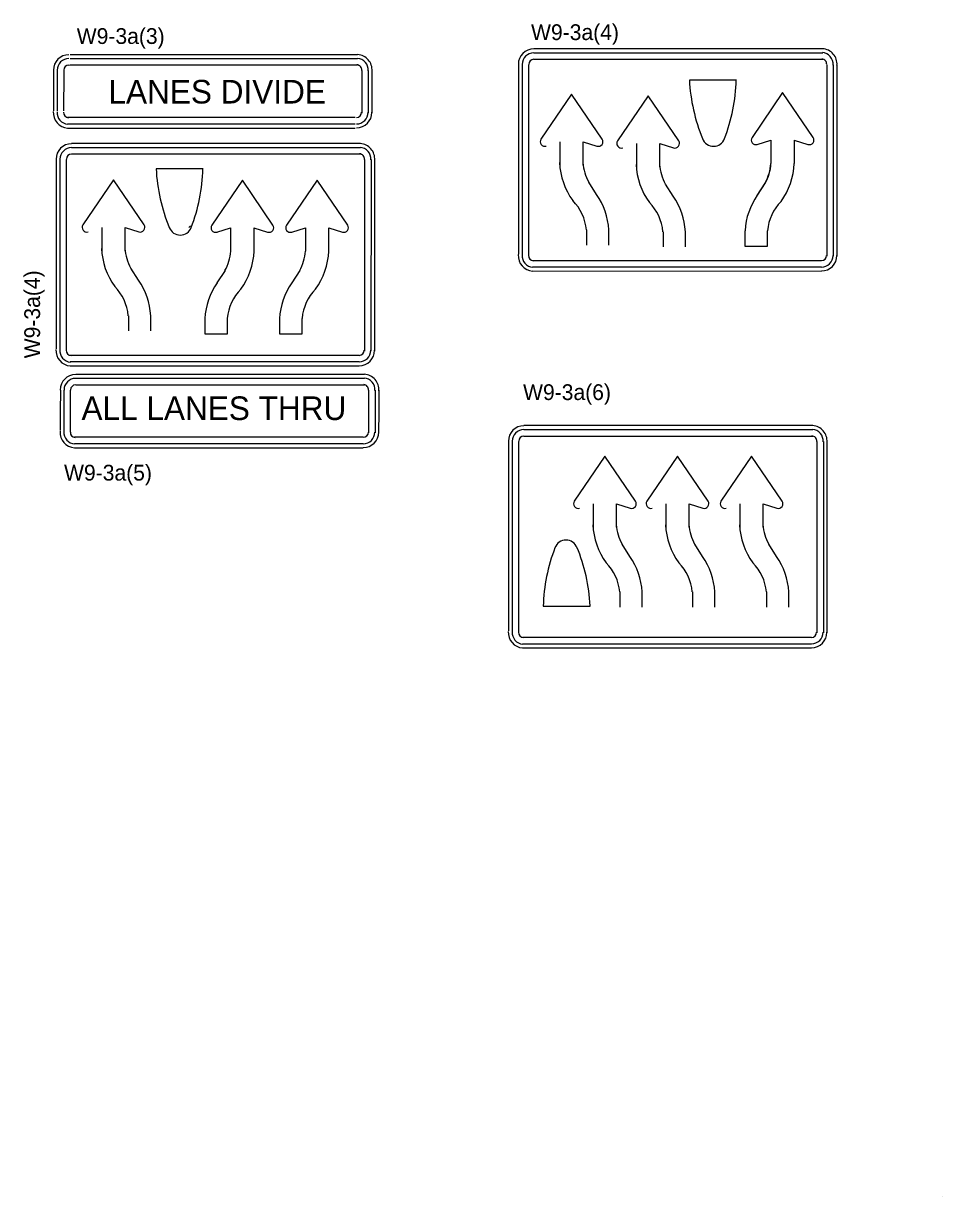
# Model space of a CAD drawing. Extents: x 1531.44 to 1538.58, y 1529.59 to 1539.3.
# Drawn here: x 1535.089 to 1538.584, y 1529.592 to 1534.054 of the extents above; entities that cross this region are included whole.
import ezdxf

# ---------------------------------------------------------------- set-up
doc = ezdxf.new("R2010")
doc.units = 0
for name, color, linetype in [('DETL-LINE', 7, 'Continuous'), ('DETL-NOTE', 7, 'Continuous'), ('TTLB-TEXT', 7, 'Continuous')]:
    doc.layers.add(name, color=color, linetype=linetype)

msp = doc.modelspace()

# ---------------------------------------------------------------- linework, layer by layer
at = {"layer": 'DETL-LINE'}
for p, q in [((1536.3596, 1533.9349), (1535.2666, 1533.9349)), ((1538.1285, 1533.9573), (1537.0299, 1533.9573)), ((1537.0299, 1533.9423), (1538.1285, 1533.9423)), ((1535.2613, 1533.8954), (1535.2658, 1533.8962)), ((1535.2658, 1533.8962), (1536.3596, 1533.8962)), ((1535.2666, 1533.9208), (1536.3596, 1533.92)), ((1536.9713, 1533.8966), (1536.9713, 1533.1767)), ((1536.9863, 1533.1736), (1536.9863, 1533.8966)), ((1537.0109, 1533.1719), (1537.0109, 1533.8966)), ((1537.0299, 1533.9177), (1538.1285, 1533.9177)), ((1537.0299, 1533.9174), (1537.0299, 1533.9177)), ((1538.1444, 1533.8966), (1538.1444, 1533.1688)), ((1538.169, 1533.8966), (1538.169, 1533.1688)), ((1538.1831, 1533.1688), (1538.1831, 1533.8966)), ((1535.2033, 1533.8751), (1535.2033, 1533.7932)), ((1535.2182, 1533.7932), (1535.2182, 1533.8751)), ((1535.242, 1533.8751), (1535.242, 1533.7932)), ((1536.3754, 1533.8751), (1536.3754, 1533.7932)), ((1536.4001, 1533.8751), (1536.4001, 1533.7932)), ((1536.415, 1533.7932), (1536.415, 1533.8751)), ((1537.8002, 1533.8381), (1537.6215, 1533.8381)), ((1535.2033, 1533.7924), (1535.2033, 1533.7211)), ((1535.2174, 1533.7211), (1535.2174, 1533.7924)), ((1535.242, 1533.7211), (1535.242, 1533.7924)), ((1536.3754, 1533.7924), (1536.3754, 1533.7123)), ((1536.4001, 1533.7924), (1536.4001, 1533.7123)), ((1536.415, 1533.7123), (1536.415, 1533.7924)), ((1537.1736, 1533.7853), (1537.0566, 1533.6137)), ((1537.2898, 1533.6137), (1537.1736, 1533.7853)), ((1537.4649, 1533.7783), (1537.3478, 1533.6067)), ((1537.581, 1533.6067), (1537.4649, 1533.7783)), ((1537.9762, 1533.7906), (1537.86, 1533.6199)), ((1538.0923, 1533.6199), (1537.9762, 1533.7906)), ((1536.3499, 1533.6956), (1535.2561, 1533.6956)), ((1536.3499, 1533.6709), (1535.2561, 1533.6709)), ((1535.2561, 1533.656), (1536.3499, 1533.656)), ((1536.3702, 1533.597), (1535.2715, 1533.597)), ((1535.2715, 1533.582), (1536.3702, 1533.582)), ((1537.1287, 1533.604), (1537.1287, 1533.5152)), ((1537.2176, 1533.5152), (1537.2176, 1533.604)), ((1537.2176, 1533.604), (1537.2695, 1533.5873)), ((1537.2695, 1533.5873), (1537.2698, 1533.5876)), ((1537.42, 1533.597), (1537.42, 1533.5081)), ((1537.5089, 1533.5081), (1537.5089, 1533.597)), ((1537.5089, 1533.597), (1537.5608, 1533.5803)), ((1537.5608, 1533.5803), (1537.5611, 1533.5805)), ((1537.8794, 1533.5935), (1537.9313, 1533.6102)), ((1537.9313, 1533.6102), (1537.9313, 1533.5213)), ((1537.9313, 1533.6093), (1537.9313, 1533.5204)), ((1538.0202, 1533.6102), (1538.0721, 1533.5935)), ((1538.021, 1533.5213), (1538.021, 1533.6102)), ((1535.213, 1533.5363), (1535.213, 1532.8164)), ((1535.2279, 1532.8131), (1535.2279, 1533.5363)), ((1535.2526, 1532.8114), (1535.2526, 1533.5363)), ((1535.2715, 1533.5574), (1536.3702, 1533.5574)), ((1535.2715, 1533.5569), (1535.2715, 1533.5574)), ((1536.386, 1533.5363), (1536.386, 1532.8076)), ((1536.4106, 1533.5363), (1536.4098, 1532.8076)), ((1536.4247, 1532.8076), (1536.4247, 1533.5363)), ((1535.5931, 1533.4993), (1535.594, 1533.5002)), ((1535.7718, 1533.5002), (1535.5931, 1533.5002)), ((1538.0206, 1533.5211), (1538.021, 1533.5213)), ((1535.4312, 1533.4588), (1535.3142, 1533.2872)), ((1535.5474, 1533.2872), (1535.4312, 1533.4588)), ((1535.9214, 1533.4571), (1535.8052, 1533.2864)), ((1536.0375, 1533.2864), (1535.9214, 1533.4571)), ((1536.2056, 1533.4571), (1536.0894, 1533.2864)), ((1536.3218, 1533.2864), (1536.2056, 1533.4571)), ((1537.2686, 1533.4034), (1537.2387, 1533.45)), ((1537.5599, 1533.3964), (1537.53, 1533.443)), ((1537.9102, 1533.4474), (1537.8794, 1533.4008)), ((1537.8794, 1533.3999), (1537.9102, 1533.4465)), ((1535.3863, 1533.2776), (1535.3863, 1533.1887)), ((1535.4752, 1533.1887), (1535.4752, 1533.2776)), ((1535.4752, 1533.2776), (1535.5271, 1533.2608)), ((1535.7172, 1533.2776), (1535.7242, 1533.2846)), ((1535.8246, 1533.26), (1535.8765, 1533.2767)), ((1535.8765, 1533.2767), (1535.8765, 1533.1878)), ((1535.9654, 1533.2767), (1536.0173, 1533.26)), ((1535.9662, 1533.1878), (1535.9662, 1533.2767)), ((1536.1088, 1533.26), (1536.1607, 1533.2767)), ((1536.1607, 1533.2767), (1536.1607, 1533.1878)), ((1536.2496, 1533.2767), (1536.3015, 1533.26)), ((1536.2505, 1533.1878), (1536.2505, 1533.2767)), ((1537.2299, 1533.2688), (1537.2299, 1533.2107)), ((1537.3153, 1533.2107), (1537.3153, 1533.2688)), ((1537.8327, 1533.2652), (1537.8327, 1533.2072)), ((1537.919, 1533.2072), (1537.919, 1533.2652)), ((1535.5271, 1533.2608), (1535.5274, 1533.2611)), ((1537.5212, 1533.2617), (1537.5212, 1533.2036)), ((1537.6066, 1533.2036), (1537.6066, 1533.2617)), ((1535.9658, 1533.1876), (1535.9662, 1533.1878)), ((1536.25, 1533.1876), (1536.2505, 1533.1878)), ((1537.3153, 1533.2107), (1537.3153, 1533.2107)), ((1537.6066, 1533.2036), (1537.6066, 1533.2036)), ((1537.8327, 1533.2072), (1537.919, 1533.2072)), ((1538.1236, 1533.1512), (1537.025, 1533.1512)), ((1535.5262, 1533.0769), (1535.4963, 1533.1236)), ((1535.8554, 1533.1139), (1535.8246, 1533.0672)), ((1536.1396, 1533.1139), (1536.1088, 1533.0672)), ((1538.1236, 1533.1266), (1537.025, 1533.1266)), ((1537.025, 1533.1125), (1538.1236, 1533.1116)), ((1535.4875, 1532.9423), (1535.4875, 1532.8842)), ((1535.5729, 1532.8842), (1535.5729, 1532.9423)), ((1535.7779, 1532.9317), (1535.7779, 1532.8736)), ((1535.8642, 1532.8736), (1535.8642, 1532.9317)), ((1536.0622, 1532.9317), (1536.0622, 1532.8736)), ((1536.1484, 1532.8736), (1536.1484, 1532.9317)), ((1535.5729, 1532.8842), (1535.5729, 1532.8842)), ((1535.7779, 1532.8736), (1535.8642, 1532.8736)), ((1536.0622, 1532.8736), (1536.1484, 1532.8736)), ((1536.3652, 1532.7909), (1535.2666, 1532.7909)), ((1536.3652, 1532.7663), (1535.2666, 1532.7663)), ((1535.2666, 1532.7513), (1536.3652, 1532.7513)), ((1536.3856, 1532.719), (1535.2872, 1532.719)), ((1535.2872, 1532.7041), (1536.3856, 1532.7041)), ((1535.2293, 1532.6592), (1535.2284, 1532.5765)), ((1535.2434, 1532.5765), (1535.2434, 1532.6592)), ((1535.268, 1532.5765), (1535.268, 1532.6592)), ((1535.2872, 1532.6794), (1536.3856, 1532.6794)), ((1535.2872, 1532.6793), (1535.2872, 1532.6794)), ((1536.4015, 1532.6592), (1536.4015, 1532.5765)), ((1536.4261, 1532.6592), (1536.4261, 1532.5765)), ((1536.4411, 1532.5765), (1536.4411, 1532.6592)), ((1535.2284, 1532.5765), (1535.2284, 1532.5052)), ((1535.2434, 1532.5017), (1535.2434, 1532.5765)), ((1535.268, 1532.4999), (1535.268, 1532.5765)), ((1536.4015, 1532.5765), (1536.4015, 1532.4964)), ((1536.4261, 1532.5765), (1536.4261, 1532.4964)), ((1536.4402, 1532.4964), (1536.4411, 1532.5765)), ((1538.0907, 1532.5242), (1536.992, 1532.5242)), ((1536.992, 1532.5092), (1538.0907, 1532.5092)), ((1536.3809, 1532.4797), (1535.2821, 1532.4797)), ((1536.9335, 1532.4635), (1536.9335, 1531.7436)), ((1536.9484, 1531.7405), (1536.9484, 1532.4635)), ((1536.9731, 1531.7388), (1536.9731, 1532.4635)), ((1536.992, 1532.4846), (1538.0907, 1532.4846)), ((1536.992, 1532.4843), (1536.992, 1532.4846)), ((1538.1065, 1532.4635), (1538.1065, 1531.7357)), ((1538.1312, 1532.4635), (1538.1312, 1531.7357)), ((1538.1452, 1531.7357), (1538.1452, 1532.4635)), ((1536.3809, 1532.455), (1535.2821, 1532.455)), ((1535.2821, 1532.4401), (1536.3809, 1532.4401)), ((1537.3003, 1532.4081), (1537.1833, 1532.2365)), ((1537.4165, 1532.2365), (1537.3003, 1532.4081)), ((1537.5766, 1532.4081), (1537.4596, 1532.2365)), ((1537.6928, 1532.2365), (1537.5766, 1532.4081)), ((1537.8582, 1532.4081), (1537.7412, 1532.2365)), ((1537.9744, 1532.2365), (1537.8582, 1532.4081)), ((1537.2554, 1532.2268), (1537.2554, 1532.138)), ((1537.3443, 1532.138), (1537.3443, 1532.2268)), ((1537.3443, 1532.2268), (1537.3962, 1532.2101)), ((1537.3962, 1532.2101), (1537.3965, 1532.2104)), ((1537.5318, 1532.2268), (1537.5318, 1532.138)), ((1537.6206, 1532.138), (1537.6206, 1532.2268)), ((1537.6206, 1532.2268), (1537.6726, 1532.2101)), ((1537.6726, 1532.2101), (1537.6728, 1532.2104)), ((1537.8134, 1532.2268), (1537.8134, 1532.138)), ((1537.9022, 1532.138), (1537.9022, 1532.2268)), ((1537.9022, 1532.2268), (1537.9542, 1532.2101)), ((1537.9542, 1532.2101), (1537.9544, 1532.2104)), ((1537.3954, 1532.0262), (1537.3654, 1532.0728)), ((1537.6717, 1532.0262), (1537.6418, 1532.0728)), ((1537.9533, 1532.0262), (1537.9234, 1532.0728)), ((1537.3566, 1531.8916), (1537.3566, 1531.8335)), ((1537.442, 1531.8335), (1537.442, 1531.8916)), ((1537.633, 1531.8916), (1537.633, 1531.8335)), ((1537.7183, 1531.8335), (1537.7183, 1531.8916)), ((1537.9146, 1531.8916), (1537.9146, 1531.8335)), ((1537.9999, 1531.8335), (1537.9999, 1531.8916)), ((1537.0654, 1531.837), (1537.244, 1531.837)), ((1537.244, 1531.837), (1537.2439, 1531.8388)), ((1537.442, 1531.8335), (1537.442, 1531.8335)), ((1537.7183, 1531.8335), (1537.7183, 1531.8335)), ((1537.9999, 1531.8335), (1537.9999, 1531.8335)), ((1538.0858, 1531.7181), (1536.9872, 1531.7181)), ((1538.0858, 1531.6935), (1536.9872, 1531.6935)), ((1536.9872, 1531.6794), (1538.0858, 1531.6785))]:
    msp.add_line(p, q, dxfattribs=at)
for centre, radius, start, end in [((1535.2613, 1533.8758), 0.059, 89.9896, 179.9896), ((1536.3556, 1533.8767), 0.059, 355.9351, 85.9351), ((1537.0299, 1533.8977), 0.059, 89.9896, 179.9896), ((1537.0299, 1533.8977), 0.0443, 89.9896, 179.9896), ((1538.1241, 1533.8987), 0.0443, 355.9351, 85.9351), ((1538.1241, 1533.8987), 0.059, 355.9351, 85.9351), ((1535.2613, 1533.8758), 0.0443, 89.9896, 179.9896), ((1535.2613, 1533.8758), 0.0197, 89.9896, 179.9896), ((1536.3556, 1533.8767), 0.0197, 355.9351, 85.9351), ((1536.3556, 1533.8767), 0.0443, 355.9351, 85.9351), ((1537.0299, 1533.8977), 0.0197, 89.9896, 179.9896), ((1538.1241, 1533.8987), 0.0197, 355.9351, 85.9351), ((1538.2892, 1533.8716), 0.6685, 182.8441, 202.5167), ((1537.1314, 1533.8562), 0.6685, 338.9042, 358.476), ((1535.2608, 1533.7147), 0.059, 175.9351, 265.9351), ((1535.2608, 1533.7147), 0.0443, 175.9351, 265.9351), ((1535.2608, 1533.7147), 0.0197, 175.9351, 265.9351), ((1536.3551, 1533.7157), 0.059, 269.9896, 359.9896), ((1536.3551, 1533.7157), 0.0443, 269.9896, 359.9896), ((1536.3551, 1533.7157), 0.0197, 269.9896, 359.9896), ((1535.2715, 1533.5372), 0.059, 89.9896, 179.9896), ((1535.2715, 1533.5372), 0.0443, 89.9896, 179.9896), ((1536.3657, 1533.5382), 0.0443, 355.9351, 85.9351), ((1536.3657, 1533.5382), 0.059, 355.9351, 85.9351), ((1537.0715, 1533.6042), 0.0175, 145.7397, 288), ((1537.2752, 1533.6042), 0.0175, 252, 34.2603), ((1537.3627, 1533.5972), 0.0175, 145.7397, 288), ((1537.5665, 1533.5972), 0.0175, 252, 34.2603), ((1537.7134, 1533.6311), 0.0446, 200.3641, 339.6359), ((1537.8742, 1533.6103), 0.0175, 145.7397, 288), ((1538.0779, 1533.6103), 0.0175, 252, 34.2603), ((1535.2715, 1533.5372), 0.0197, 89.9896, 179.9896), ((1536.3657, 1533.5382), 0.0197, 355.9351, 85.9351), ((1536.2608, 1533.5337), 0.6685, 182.8441, 202.5167), ((1535.103, 1533.5183), 0.6685, 338.9042, 358.476), ((1537.3948, 1533.5362), 0.2674, 182.5554, 215.8093), ((1537.3948, 1533.5362), 0.1784, 183.8322, 208.8162), ((1537.686, 1533.5292), 0.2674, 182.5554, 215.8093), ((1537.686, 1533.5292), 0.1784, 183.8322, 208.8162), ((1537.7535, 1533.5331), 0.1784, 331.1838, 356.1678), ((1537.7538, 1533.5323), 0.1784, 331.1838, 356.1678), ((1537.7535, 1533.5331), 0.2674, 324.1907, 357.4446), ((1537.0506, 1533.2531), 0.265, 3.3657, 34.6128), ((1538.0977, 1533.2499), 0.265, 145.3872, 176.6343), ((1537.0506, 1533.2531), 0.1797, 4.968, 44.8693), ((1537.3419, 1533.246), 0.1797, 4.968, 44.8693), ((1537.3419, 1533.246), 0.265, 3.3657, 34.6128), ((1538.0977, 1533.2499), 0.1797, 135.1307, 175.032), ((1535.3291, 1533.2777), 0.0175, 145.7397, 288), ((1535.5328, 1533.2777), 0.0175, 252, 34.2603), ((1535.685, 1533.2932), 0.0446, 200.3641, 339.6359), ((1535.8194, 1533.2768), 0.0175, 145.7397, 288), ((1536.0231, 1533.2768), 0.0175, 252, 34.2603), ((1536.1036, 1533.2768), 0.0175, 145.7397, 288), ((1536.3073, 1533.2768), 0.0175, 252, 34.2603), ((1535.6524, 1533.2098), 0.2674, 182.5554, 215.8093), ((1535.6524, 1533.2098), 0.1784, 183.8322, 208.8162), ((1535.6987, 1533.1995), 0.1784, 331.1838, 356.1678), ((1535.6987, 1533.1995), 0.2674, 324.1907, 357.4446), ((1535.9829, 1533.1995), 0.1784, 331.1838, 356.1678), ((1535.9829, 1533.1995), 0.2674, 324.1907, 357.4446), ((1537.0294, 1533.1705), 0.059, 175.9351, 265.9351), ((1537.0294, 1533.1705), 0.0443, 175.9351, 265.9351), ((1537.0294, 1533.1705), 0.0197, 175.9351, 265.9351), ((1538.1236, 1533.1714), 0.059, 269.9896, 359.9896), ((1538.1236, 1533.1714), 0.0443, 269.9896, 359.9896), ((1538.1236, 1533.1714), 0.0197, 269.9896, 359.9896), ((1535.3082, 1532.9266), 0.1797, 4.968, 44.8693), ((1535.3082, 1532.9266), 0.265, 3.3657, 34.6128), ((1536.0429, 1532.9163), 0.265, 145.3872, 176.6343), ((1536.0429, 1532.9163), 0.1797, 135.1307, 175.032), ((1536.3271, 1532.9163), 0.265, 145.3872, 176.6343), ((1536.3271, 1532.9163), 0.1797, 135.1307, 175.032), ((1535.2709, 1532.81), 0.059, 175.9351, 265.9351), ((1535.2709, 1532.81), 0.0443, 175.9351, 265.9351), ((1535.2709, 1532.81), 0.0197, 175.9351, 265.9351), ((1536.3652, 1532.8109), 0.059, 269.9896, 359.9896), ((1536.3652, 1532.8109), 0.0443, 269.9896, 359.9896), ((1536.3652, 1532.8109), 0.0197, 269.9896, 359.9896), ((1535.2871, 1532.6596), 0.059, 89.9896, 179.9896), ((1535.2871, 1532.6596), 0.0443, 89.9896, 179.9896), ((1536.3814, 1532.6606), 0.0443, 355.9351, 85.9351), ((1536.3814, 1532.6606), 0.059, 355.9351, 85.9351), ((1535.2871, 1532.6596), 0.0197, 89.9896, 179.9896), ((1536.3814, 1532.6606), 0.0197, 355.9351, 85.9351), ((1536.992, 1532.4646), 0.059, 89.9896, 179.9896), ((1536.992, 1532.4646), 0.0443, 89.9896, 179.9896), ((1538.0863, 1532.4656), 0.0443, 355.9351, 85.9351), ((1538.0863, 1532.4656), 0.059, 355.9351, 85.9351), ((1535.2866, 1532.4985), 0.059, 175.9351, 265.9351), ((1535.2866, 1532.4985), 0.0443, 175.9351, 265.9351), ((1535.2866, 1532.4985), 0.0197, 175.9351, 265.9351), ((1536.3809, 1532.4995), 0.059, 269.9896, 359.9896), ((1536.3809, 1532.4995), 0.0443, 269.9896, 359.9896), ((1536.3809, 1532.4995), 0.0197, 269.9896, 359.9896), ((1536.992, 1532.4646), 0.0197, 89.9896, 179.9896), ((1538.0863, 1532.4656), 0.0197, 355.9351, 85.9351), ((1537.1982, 1532.227), 0.0175, 145.7397, 288), ((1537.4019, 1532.227), 0.0175, 252, 34.2603), ((1537.4745, 1532.227), 0.0175, 145.7397, 288), ((1537.6782, 1532.227), 0.0175, 252, 34.2603), ((1537.7561, 1532.227), 0.0175, 145.7397, 288), ((1537.9598, 1532.227), 0.0175, 252, 34.2603), ((1537.5215, 1532.159), 0.2674, 182.5554, 215.8093), ((1537.5215, 1532.159), 0.1784, 183.8322, 208.8162), ((1537.7978, 1532.159), 0.2674, 182.5554, 215.8093), ((1537.7978, 1532.159), 0.1784, 183.8322, 208.8162), ((1538.0794, 1532.159), 0.2674, 182.5554, 215.8093), ((1538.0794, 1532.159), 0.1784, 183.8322, 208.8162), ((1537.734, 1531.8193), 0.6685, 158.9042, 178.476), ((1537.152, 1532.0445), 0.0446, 20.3641, 159.6359), ((1536.5762, 1531.8056), 0.6685, 2.8441, 22.5167), ((1537.1773, 1531.8759), 0.265, 3.3657, 34.6128), ((1537.4536, 1531.8759), 0.265, 3.3657, 34.6128), ((1537.7352, 1531.8759), 0.265, 3.3657, 34.6128), ((1537.1773, 1531.8759), 0.1797, 4.968, 44.8693), ((1537.4536, 1531.8759), 0.1797, 4.968, 44.8693), ((1537.7352, 1531.8759), 0.1797, 4.968, 44.8693), ((1536.9915, 1531.7374), 0.059, 175.9351, 265.9351), ((1536.9915, 1531.7374), 0.0443, 175.9351, 265.9351), ((1536.9915, 1531.7374), 0.0197, 175.9351, 265.9351), ((1538.0858, 1531.7384), 0.059, 269.9896, 359.9896), ((1538.0858, 1531.7384), 0.0443, 269.9896, 359.9896), ((1538.0858, 1531.7384), 0.0197, 269.9896, 359.9896)]:
    msp.add_arc(centre, radius, start, end, dxfattribs=at)
at = {"layer": 'TTLB-TEXT'}
msp.add_line((1538.5844, 1529.5923), (1538.5844, 1529.5923), dxfattribs=at)

# ---------------------------------------------------------------- texts
at = {"layer": 'DETL-LINE'}
for s, p in [('LANES DIVIDE', (1535.4118, 1533.7492)), ('ALL LANES THRU', (1535.3092, 1532.5454))]:
    msp.add_text(s, height=0.08976, dxfattribs=at).set_placement(p)
at = {"layer": 'DETL-NOTE'}
for s, p in [('W9-3a(3)', (1535.2912, 1533.9757)), ('W9-3a(4)', (1537.0192, 1533.9904)), ('W9-3a(6)', (1536.9888, 1532.6214)), ('W9-3a(5)', (1535.2429, 1532.3152))]:
    msp.add_text(s, height=0.06, dxfattribs=at).set_placement(p)
msp.add_text('W9-3a(4)', height=0.06, rotation=90, dxfattribs=at).set_placement((1535.1517, 1532.7802))

doc.saveas('drawing.dxf')
